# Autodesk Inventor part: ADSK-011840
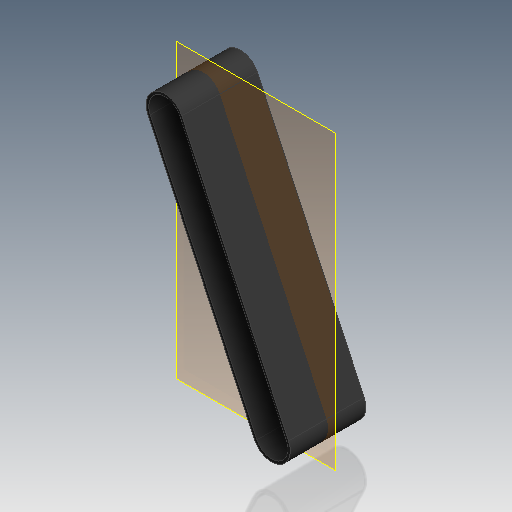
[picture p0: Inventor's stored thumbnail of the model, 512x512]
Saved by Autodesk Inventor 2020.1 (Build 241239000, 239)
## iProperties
Created: 2000-03
Part Number: ADSK-011840
Material: Pearson HRS
Description: CHAIN,MATTOP,FLUSH GRID,9.00W X 1.00 PITCH, LF, 2100 SERIES
Document SubType Name: Modeling
Designer: cmcgourin
Density: 7.83 g/cm^3
Appearance: Rubber-Black
Mass: 26905.2 g
Surface Area: 8889.21 cm^2
Volume: 3436.16 cm^3
Control State: 0
Master: False
Checked Out: False
Shininess: 0.0
Length Units: 11269
Angle Units: 11279
Time Units: 11290
Mass Units: 11283
Length Display Precision: 3
Angle Display Precision: 2
Compacted: True
Cutlength: 23.25
Material Desc: Material Description goes here
Material_Number: Pearson
Dimensions: 808,9x230x439,1 mm
Mass: 26,905 kg
VLT_Material: Pearson HRS
DocNumber: ADSK-011840.ipt
Folder: 01 - Themengebiete\Simplification\01 - Packaging machine\
VDS_Category: 3D Komponenten
Density: 0.0
Volumn: 0.0
Area: 0.0
PropertySet Name: Model Information
Author: cmcgourin
Revision Number: -
Title: belt
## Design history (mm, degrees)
workplane "Arbeitsebene2"
node "Solide1"
  node "Extrusion1" dims "d2" = 230, "d3" = 0
sketch "Sketch1"
  geometry: L1 (302.853, -788.429)-(-22.127, -93.68); L2 (258.401, -809.222)-(-66.579, -114.473); L3 (22.325, -72.887)-(347.305, -767.636); L4 (354.552, -764.246)-(29.571, -69.497); L5 (-73.826, -117.863)-(251.155, -812.612); C1 r 49.075 at (302.853, -788.429) reference; C2 r 49.075 at (-22.127, -93.68) reference; A1 r 49.075 centre (302.853, -788.429) between (258.401, -809.222) and (347.305, -767.636); A2 r 49.075 centre (-22.127, -93.68) between (22.325, -72.887) and (-66.579, -114.473); A3 r 57.075 centre (-22.127, -93.68) between (29.571, -69.497) and (-73.826, -117.863); A4 r 57.075 centre (302.853, -788.429) between (251.155, -812.612) and (354.552, -764.246); 1 further point
  constraints: 12 end point, 8 point on circle, 4 centre point, 4 tangent, 2 parallel, 1 concentric, 1 midpoint, 3 other
  dimensions: "d4" = 8 distance between parallel lines of L3 L4
feature "Fläche1"
node "Flä1"
feature "Fläche2"
node "Flä2"
feature "Fläche3"
node "Flä3"
feature "Fläche4"
node "Flä4"
workplane "Arbeitsebene1"
node "Corps solides"
node "Corps surfaciques"
